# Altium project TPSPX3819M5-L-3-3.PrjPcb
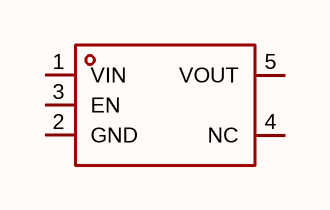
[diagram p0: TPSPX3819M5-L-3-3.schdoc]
1 sheet, 1 parts. Net scope: global (net labels, ports and power ports of the same name join across sheets).

## Sheet TPSPX3819M5-L-3-3.schdoc
size 127 x 101 mm

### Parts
U?  tpspx3819m5-l-3-3  [SOT-23-5_L3.0-W1.6-P0.95-LS2.8-BR]  (value not drawn)

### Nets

Not connected (* = marked no-connect by the designer): U? 1(VIN) 2(GND) 3(EN) 4(NC) 5(VOUT)

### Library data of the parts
U? = tpspx3819m5-l-3-3: 输出极性:正极;工作电压:20V;输出电压:3.3V;输出电流:500mA;电源纹波抑制比(PSRR):70dB@(1kHz);输出类型:固定;; Manufacturer: TECH PUBLIC(台舟); AddInBom: yes; ModelId: 72410e292833493f86746b22636ce101; ModelTransform: 110.236,116.1415,0,0,0,0,0.002,0.001,0; Output Configuration: 正极; Voltage - Supply: 20V; Output Voltage: 3.3V; Output Current: 500mA; Voltage Dropout: 420mV@(100mA); standby current: 5uA; Output Type: 固定; Number of Outputs: 1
